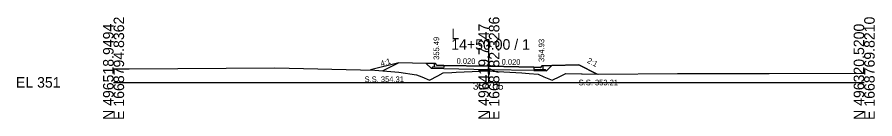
# Model space of a CAD drawing. Extents: x -26 to 203, y -10 to 5517.
# Drawn here: x -25.7 to 202.8, y 4490.3 to 4517.3 of the extents above; entities that cross this region are included whole.
import ezdxf

# ---------------------------------------------------------------- set-up
doc = ezdxf.new("R2010")
doc.units = 0
for name, color, linetype in [('Exist Cross Section Cell', 7, 'Continuous'), ('Exist XS Center Line Elevation Label', 7, 'Continuous'), ('Exist XS Ground Line', 7, 'Continuous'), ('Prop XS Earthwork Shape', 7, 'Continuous'), ('Prop XS Finish Grade', 7, 'Continuous'), ('Prop XS Finish Grade CurbGutter', 7, 'Continuous'), ('Prop XS Finish Grade Earthwork', 7, 'Continuous'), ('Prop XS Finish Grade Pavement', 7, 'Continuous'), ('Prop XS Geopak Shape', 7, 'Continuous'), ('Prop XS Hydro Elevations', 7, 'Continuous'), ('Prop XS Pvmt Edge Slope', 7, 'Continuous'), ('Prop XS SE Text', 7, 'Continuous'), ('Prop XS Side Slope Text', 7, 'Continuous'), ('Prop XS SS Elevation Text', 7, 'Continuous'), ('Prop XS Subgrade CurbGutter', 7, 'Continuous'), ('Prop XS Subgrade Earthwork', 7, 'Continuous')]:
    doc.layers.add(name, color=color, linetype=linetype)

msp = doc.modelspace()

# ---------------------------------------------------------------- linework, layer by layer
at = {"layer": 'Exist Cross Section Cell'}
for p, q in [((100, 4500), (100, 4511.49)), ((0, 4500), (100, 4500)), ((100, 4500), (200, 4500))]:
    msp.add_line(p, q, dxfattribs=at)
at = {"layer": 'Exist XS Ground Line'}
for p, q in [((0, 4503.61), (4.16, 4503.64)), ((4.16, 4503.64), (42.99, 4503.83)), ((42.99, 4503.83), (69.61, 4503.28)), ((69.61, 4503.28), (75.99, 4502.68)), ((75.99, 4502.68), (80.7, 4502.04)), ((86.37, 4501.75), (87.83, 4502.53)), ((87.83, 4502.53), (90.14, 4502.66)), ((90.14, 4502.66), (91.29, 4502.7)), ((91.29, 4502.7), (93.42, 4502.78)), ((93.42, 4502.78), (99.92, 4503.05)), ((99.92, 4503.05), (102.41, 4502.93)), ((102.41, 4502.93), (108.75, 4502.58)), ((108.75, 4502.58), (110.75, 4502.4)), ((110.75, 4502.4), (113.09, 4502.15)), ((113.09, 4502.15), (114.67, 4501.44)), ((118.87, 4501.52), (120.51, 4502.33)), ((120.51, 4502.33), (129.2, 4502.2)), ((129.2, 4502.2), (150.25, 4502.38)), ((150.25, 4502.38), (174.64, 4502.33)), ((174.64, 4502.33), (197.86, 4502.44)), ((197.86, 4502.44), (200, 4502.38)), ((80.7, 4502.04), (82.16, 4501.43)), ((82.16, 4501.43), (84.19, 4500.62)), ((84.19, 4500.62), (86.37, 4501.75)), ((114.67, 4501.44), (116.84, 4500.56)), ((116.84, 4500.56), (118.87, 4501.52))]:
    msp.add_line(p, q, dxfattribs=at)
at = {"layer": 'Prop XS Earthwork Shape'}
msp.add_lwpolyline([(112, 4503.13), (100, 4503.37), (88, 4503.61), (84.67, 4503.68), (83.31, 4505.03), (76, 4505.19), (71.78, 4503.08), (75.99, 4502.68), (80.7, 4502.04), (82.16, 4501.43), (84.19, 4500.62), (86.37, 4501.75), (87.83, 4502.53), (90.14, 4502.66), (91.29, 4502.7), (93.42, 4502.78), (99.92, 4503.05), (102.41, 4502.93), (108.75, 4502.58), (110.75, 4502.4), (113.09, 4502.15), (114.67, 4501.44), (116.84, 4500.56), (118.87, 4501.52), (120.51, 4502.33), (128.84, 4502.21), (124, 4504.63), (116.74, 4504.48), (115.33, 4503.07)], close=True, dxfattribs=at)
at = {"layer": 'Prop XS Finish Grade'}
for p, q in [((85.5, 4504.99), (83.31, 4505.03)), ((114.5, 4504.43), (116.74, 4504.48))]:
    msp.add_line(p, q, dxfattribs=at)
at = {"layer": 'Prop XS Finish Grade CurbGutter'}
for p, q in [((85.5, 4504.99), (85.75, 4504.99)), ((85.75, 4504.99), (85.88, 4504.95)), ((85.97, 4504.86), (85.88, 4504.95)), ((86.03, 4504.61), (85.97, 4504.86)), ((86.13, 4504.52), (86.03, 4504.61)), ((86.25, 4504.49), (86.13, 4504.52)), ((88, 4504.53), (86.25, 4504.49)), ((114.03, 4504.31), (114.12, 4504.4)), ((114.25, 4504.43), (114.12, 4504.4)), ((114.5, 4504.43), (114.25, 4504.43)), ((112, 4504.05), (113.75, 4503.94)), ((113.75, 4503.94), (113.87, 4503.97)), ((113.87, 4503.97), (113.97, 4504.06)), ((113.97, 4504.06), (114.03, 4504.31))]:
    msp.add_line(p, q, dxfattribs=at)
at = {"layer": 'Prop XS Finish Grade Earthwork'}
for p, q in [((76, 4505.19), (68.48, 4503.31)), ((83.31, 4505.03), (76, 4505.19)), ((116.74, 4504.48), (124, 4504.63)), ((124, 4504.63), (128.84, 4502.21))]:
    msp.add_line(p, q, dxfattribs=at)
at = {"layer": 'Prop XS Finish Grade Pavement'}
for p, q in [((88, 4504.53), (100, 4504.29)), ((100, 4504.29), (112, 4504.05))]:
    msp.add_line(p, q, dxfattribs=at)
at = {"layer": 'Prop XS Geopak Shape'}
msp.add_lwpolyline([(71.78, 4503.08), (75.99, 4502.68), (80.7, 4502.04), (82.16, 4501.43), (84.19, 4500.62), (86.37, 4501.75), (87.83, 4502.53), (90.14, 4502.66), (91.29, 4502.7), (93.42, 4502.78), (99.92, 4503.05), (102.41, 4502.93), (108.75, 4502.58), (110.75, 4502.4), (113.09, 4502.15), (114.67, 4501.44), (116.84, 4500.56), (118.87, 4501.52), (120.51, 4502.33), (128.84, 4502.21), (124, 4504.63), (116.74, 4504.48), (114.5, 4504.43), (114.25, 4504.43), (114.12, 4504.4), (114.03, 4504.31), (113.97, 4504.06), (113.87, 4503.97), (113.75, 4503.94), (112, 4504.05), (100, 4504.29), (88, 4504.53), (86.25, 4504.49), (86.13, 4504.52), (86.03, 4504.61), (85.97, 4504.86), (85.88, 4504.95), (85.75, 4504.99), (85.5, 4504.99), (83.31, 4505.03), (76, 4505.19)], close=True, dxfattribs=at)
at = {"layer": 'Prop XS Pvmt Edge Slope'}
for p, q in [((85, 4504.01), (84.67, 4503.68)), ((85.5, 4504), (85, 4504.01)), ((114.5, 4503.42), (115, 4503.41)), ((115, 4503.41), (115.33, 4503.07))]:
    msp.add_line(p, q, dxfattribs=at)
at = {"layer": 'Prop XS Subgrade CurbGutter'}
for p, q in [((85.5, 4504), (85.5, 4504.99)), ((88, 4504.53), (88, 4503.95)), ((114.5, 4503.42), (114.5, 4504.43)), ((88, 4503.95), (85.5, 4504)), ((112, 4504.05), (112, 4503.47)), ((112, 4503.47), (114.5, 4503.42))]:
    msp.add_line(p, q, dxfattribs=at)
at = {"layer": 'Prop XS Subgrade Earthwork'}
for p, q in [((84.67, 4503.68), (83.31, 4505.03)), ((115.33, 4503.07), (116.74, 4504.48)), ((88, 4503.61), (84.67, 4503.68)), ((88, 4503.61), (88, 4503.61)), ((100, 4503.37), (88, 4503.61)), ((112, 4503.13), (100, 4503.37)), ((112, 4503.13), (112, 4503.13)), ((112, 4503.13), (115.33, 4503.07))]:
    msp.add_line(p, q, dxfattribs=at)

# ---------------------------------------------------------------- texts
at = {"layer": 'Exist Cross Section Cell'}
for s, p in [('E 1668794.8362', (2.8, 4490)), ('E 1668782.3286', (102.8, 4490)), ('E 1668769.8210', (202.8, 4490)), ('N 496518.9494', (0, 4490)), ('N 496419.7347', (100, 4490)), ('N 496320.5200', (200, 4490))]:
    msp.add_text(s, height=2.8, rotation=90, dxfattribs=at).set_placement(p)
for s, p in [('L', (90, 4511.49)), ('14+50.00 / 1', (90, 4508.69)), ('EL 351', (-26, 4498.6))]:
    msp.add_text(s, height=2.8, dxfattribs=at).set_placement(p)
at = {"layer": 'Exist XS Center Line Elevation Label'}
msp.add_text('354.05', height=2, dxfattribs=at).set_placement((95.74, 4498.05))
at = {"layer": 'Prop XS Hydro Elevations'}
for s, p in [('355.49', (86.75, 4505.99)), ('354.93', (114.75, 4505.43))]:
    msp.add_text(s, height=1.5, rotation=90, dxfattribs=at).set_placement(p)
at = {"layer": 'Prop XS SE Text'}
for p in [(91.38, 4504.96), (103.38, 4504.72)]:
    msp.add_text('0.020', height=1.5, rotation=358.8542, dxfattribs=at).set_placement(p)
at = {"layer": 'Prop XS Side Slope Text'}
for s, rotation, p in [('4:1', 17.6471, (71.36, 4504.19)), ('2:1', 333.4349, (126.03, 4505.29))]:
    msp.add_text(s, height=1.5, rotation=rotation, dxfattribs=at).set_placement(p)
at = {"layer": 'Prop XS SS Elevation Text'}
for s, p in [('S.S. 354.31', (66.87, 4500.08)), ('S.S. 353.21', (123.93, 4499.21))]:
    msp.add_text(s, height=1.5, dxfattribs=at).set_placement(p)

doc.saveas('drawing.dxf')
